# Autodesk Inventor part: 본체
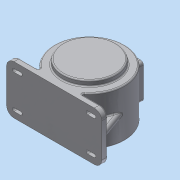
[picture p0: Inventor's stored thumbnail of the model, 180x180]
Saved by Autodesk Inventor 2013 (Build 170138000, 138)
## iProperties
Created: 2415-06
Part Number: 본체
Material: 알루미늄 6061
Document SubType Name: Modeling
Designer: Administrator
Density: 2.71 g/cm^3
Mass: 3262.64 g
Surface Area: 2294.84 cm^2
Volume: 1203.93 cm^3
Author: Administrator
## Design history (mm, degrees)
sketch "스케치1"
  geometry: C1 r 85 at (0, 0); 1 further point
  constraints: 1 centre point, 1 coincident
  dimensions: "d0" = 170 diameter of C1
extrude "돌출1" new body sketch "스케치1" stored distance "d3" = 118; taper "d4" = 0 deg
sketch "스케치2"
  geometry: C1 r 85 at (0, 0) reference; C2 r 65 at (0, 0)
  constraints: 1 centre point, 1 coincident
  dimensions: "d5" = 130 diameter of C2
extrude "돌출2" join sketch "스케치2" distance "d7" = 13; taper "d8" = 0 deg
sketch "스케치3"
  geometry: C1 r 85 at (0, 0) reference; C2 r 65 at (0, 0)
  constraints: 1 centre point, 1 coincident
  dimensions: "d9" = 130 diameter of C2
extrude "돌출3" join sketch "스케치3" distance "d11" = 3; taper "d12" = 0 deg
node "작업 평면1"
sketch "스케치4"
  geometry: L1 (-97, -59)-(97, -59); L2 (115, -41)-(115, 41); L3 (97, 59)-(-97, 59); L4 (-115, 41)-(-115, -41); L5 (-115, -59)-(115, 59); L6 (115, -59)-(-115, 59); A1 r 18 centre (-97, 41) between (-97, 59) and (-115, 41); A2 r 18 centre (-97, -41) between (-115, -41) and (-97, -59); A3 r 18 centre (97, -41) between (97, -59) and (115, -41); A4 r 18 centre (97, 41) between (115, 41) and (97, 59); 3 further points
  constraints: 12 end point, 8 point on circle, 8 point on line, 8 tangent, 4 centre point, 3 equal radius, 3 midpoint, 2 parallel, 1 coincident, 1 horizontal, 1 perpendicular
  dimensions: "d14" = 230 distance of L6.end L5.end; "d15" = 118 distance of L5.end L6.start; "d16" = 18 radius of A1
extrude "돌출4" join sketch "스케치4" distance "d17" = 14; taper "d18" = 0 deg
sketch "스케치5"
  geometry: L1 (0, 41)-(0, -41); L2 (97, 41)-(97, -41); L3 (-97, 41)-(-97, -41); L4 (-97, 50)-(-81, 50); L5 (-97, 32)-(-81, 32); L6 (-81, 45)-(-97, 45); L7 (-97, 37)-(-81, 37); A1 r 9 centre (-97, 41) between (-97, 50) and (-97, 32); A2 r 9 centre (-81, 41) between (-81, 32) and (-81, 50); A3 r 4 centre (-97, 41) between (-97, 45) and (-97, 37); A4 r 4 centre (-81, 41) between (-81, 37) and (-81, 45); 2 further points
  constraints: 14 end point, 8 point on circle, 4 centre point, 4 parallel, 2 coincident, 2 tangent, 1 midpoint, 1 perpendicular, 1 vertical, 3 other
  dimensions: "d19" = 82 distance of L1.start L1.end; "d20" = 97 distance between parallel lines of L3 L1; "d21" = 97 distance between parallel lines of L2 L1 (= d20); "d22" = 18 diameter of A1; "d23" = 16 distance of L4.start L4.end; "d24" = 16 distance of L5.start L5.end; "d25" = 97 distance of L1.start L3.start; "d26" = 81 distance of L1.start A2.centre; "d27" = 8 distance between parallel lines of L6 L7
extrude "돌출5" cut sketch "스케치5" stored distance "d28" = 14; taper "d29" = 0 deg
extrude "돌출6" join sketch "스케치5" distance "d30" = 3; taper "d31" = 0 deg
fillet "모깎기1" dims "d32" = 3
hole "구멍1" diameter "d35" = 95; stored, may be unused: countersink angle "d39" = 90 deg, drill point angle "d41" = 0 deg; dims "d33" = 10, "d34" = 10, "d36" = 6, "d37" = 95, "d38" = 11, "d40" = 11
hole "구멍2" diameter "d44" = 154; stored, may be unused: countersink angle "d48" = 90 deg, drill point angle "d50" = 0 deg; dims "d45" = 6, "d46" = 95, "d47" = 11, "d49" = 98.5, "d120" = 10, "d121" = 10
hole "구멍3" diameter "d53" = 30; stored, may be unused: countersink angle "d57" = 90 deg, drill point angle "d59" = 0 deg; dims "d51" = 10, "d52" = 10, "d54" = 6, "d55" = 47, "d56" = 14, "d58" = 17
node "작업 평면2"
sketch "스케치6"
  geometry: L1 (-35.5, -42.5)-(35.5, -42.5); L2 (42.5, -35.5)-(42.5, 35.5); L3 (35.5, 42.5)-(-35.5, 42.5); L4 (-42.5, 35.5)-(-42.5, -35.5); L5 (-42.5, -42.5)-(42.5, 42.5); L6 (42.5, -42.5)-(-42.5, 42.5); A1 r 7 centre (-35.5, 35.5) between (-35.5, 42.5) and (-42.5, 35.5); A2 r 7 centre (-35.5, -35.5) between (-42.5, -35.5) and (-35.5, -42.5); A3 r 7 centre (35.5, -35.5) between (35.5, -42.5) and (42.5, -35.5); A4 r 7 centre (35.5, 35.5) between (42.5, 35.5) and (35.5, 42.5); 1 further point
  constraints: 12 end point, 8 point on circle, 8 point on line, 8 tangent, 4 centre point, 3 equal radius, 2 midpoint, 2 parallel, 1 horizontal, 1 perpendicular
  dimensions: "d61" = 85 distance of L5.end L6.end; "d63" = 85 distance of L6.start L5.end; "d64" = 7 radius of A1
extrude "돌출7" join sketch "스케치6" stored distance "d65" = 3; taper "d66" = 0 deg
sketch "스케치7"
  geometry: C1 r 35 at (0, 0); 1 further point
  constraints: 1 centre point, 1 coincident
  dimensions: "d67" = 70 diameter of C1
extrude "돌출8" cut sketch "스케치7" stored distance "d69" = 3; taper "d70" = 0 deg
sketch "스케치8"
  geometry: A1 r 55 centre (0, 0) between (0, 55) and (-55, 0); 3 further points
  constraints: 4 point on circle, 2 horizontal alignment, 2 vertical alignment, 1 centre point
  dimensions: "d71" = 110 diameter of A1
hole "구멍4" sketch "스케치8" at (0, 55), (-55, 0), (0, -55), (55, 0) diameter "d73" = 3.242; stored, may be unused: countersink angle "d77" = 90 deg, drill point angle "d79" = 0 deg; dims "d74" = 6, "d75" = 19.05, "d76" = 4.775, "d78" = 17
hole "구멍5" diameter "d82" = 3.242; stored, may be unused: countersink angle "d86" = 90 deg, drill point angle "d88" = 0 deg; dims "d80" = 10, "d81" = 10, "d83" = 10, "d84" = 19.05, "d85" = 4.775, "d87" = 13
hole "구멍6" diameter "d91" = 3.242; stored, may be unused: countersink angle "d95" = 90 deg, drill point angle "d97" = 0 deg; dims "d89" = 10, "d90" = 10, "d92" = 10, "d93" = 19.05, "d94" = 4.775, "d96" = 13
hole "구멍7" diameter "d100" = 3.242; stored, may be unused: countersink angle "d104" = 90 deg, drill point angle "d106" = 0 deg; dims "d98" = 10, "d99" = 10, "d101" = 10, "d102" = 19.05, "d103" = 4.775, "d105" = 13
hole "구멍8" diameter "d109" = 3.242; stored, may be unused: countersink angle "d113" = 90 deg, drill point angle "d115" = 0 deg; dims "d107" = 10, "d108" = 10, "d110" = 10, "d111" = 19.05, "d112" = 4.775, "d114" = 13
fillet "모깎기2" dims "d116" = 0.3
fillet "모깎기4" dims "d118" = 3
fillet "모깎기5" dims "d119" = 3
sketch "스케치9"
  geometry: L1 (-77, 47.5)-(77, 47.5) reference; L2 (0, -67.8)-(0, 70.8) reference; L3 (77, 51)-(77, 47.5); L4 (77, 47.5)-(77, -48) reference; L5 (31, 47.5)-(31, 51); L6 (31, 51)-(29.368, 47.5); L7 (31, 51)-(77, 51); 1 further point
  constraints: 8 end point, 2 parallel, 2 point on line, 1 perpendicular
  dimensions: "d123" = 62 diameter of L5 L2; "d126" = 3.5 distance of L3.start L1.end; "d127" = 115 deg angle of L7 L6
revolve "회전1" sketch "스케치9" stored, may be unused: angle "d128" = 90 deg
sketch "스케치10"
  geometry: 1 further point
fillet "모깎기6" dims "d129" = 3
chamfer "모따기1" distance "d130" = 1; stored, may be unused: second distance "d131" = 2, angle "d132" = 45 deg
chamfer "모따기2" distance "d133" = 1; stored, may be unused: second distance "d134" = 2, angle "d135" = 45 deg
sketch "스케치11"
  geometry: L1 (-115, -85)-(-115, -71) reference; L2 (-97, -71)-(-115, -71) reference; L3 (-97, -71)-(-81, -71) reference; L4 (-115, -85)-(-97, -85) reference; L5 (-109, -71)-(-109, -85); L6 (-69, -71)-(-81, -71) reference; L7 (-46.733, -71)-(-97, -71) reference; L8 (-109, -71)-(-84.87, -4.703); A1 r 85 centre (0, 0) between (46.733, -71) and (-46.733, -71) reference; 1 further point
  constraints: 4 end point, 2 point on line, 1 perpendicular, 1 point on circle
  dimensions: "d141" = 6 distance between parallel lines of L5 L1; "d142" = 110 deg angle of L8 L2
extrude "돌출10" join sketch "스케치11" stored distance "d143" = 15; taper "d144" = 0 deg
fillet "모깎기7" dims "d145" = 3
fillet "모깎기8"
fillet "모깎기9"
fillet "모깎기10" dims "d146" = 3
fillet "모깎기11" dims "d147" = 3
sketch "스케치12"
  geometry: L1 (-161, 0)-(161, 0) reference; L2 (0, 0)-(182.329, 85.021); L3 (56.726, 79.477)-(94.457, -1.436); A1 r 85 centre (0, 0) between (53.953, -65.682) and (-53.953, -65.682) reference
  constraints: 4 end point, 1 perpendicular, 1 tangent
  dimensions: "d148" = 25 deg angle of L2 L1; "d149" = 201.17745 distance of L2.start L2.end; "d150" = 89.27744 distance of L3.start L3.end
node "작업 평면3"
fillet "모깎기12" dims "d154" = 3
sketch "스케치14"
  geometry: L1 (0, 0)-(-115.997, 54.09); L2 (-176.87, 0)-(242.195, 0) reference; L3 (-65.415, 60.843)-(-88.657, 11.002); A1 r 85 centre (0, 0) between (53.953, -65.682) and (-53.953, -65.682) reference; 1 further point
  constraints: 4 end point, 1 midpoint, 1 perpendicular, 1 point on line, 1 tangent
  dimensions: "d155" = 25 deg angle of L1 L2; "d158" = 115.9966 horizontal distance of L1.start L1.end; "d159" = 54.99423 distance of L3.start L3.end
node "작업 평면4"
sketch "스케치15"
  geometry: 2 further points
  constraints: 1 coincident, 1 other
feature "엠보싱2" sketch "스케치15" dims "d160" = 0.5, "d161" = 0
chamfer "모따기3" distance "d162" = 1; stored, may be unused: second distance "d163" = 2, angle "d164" = 45 deg
fillet "모깎기13" dims "d165" = 3
fillet "모깎기14" dims "d166" = 0.3
node "솔리드1"
mirror "대칭1"
mirror "대칭2"
mirror "대칭3"
other parameters: "d13" = -85, "d60" = 88, "d122" = 3.5, "d125" = 115 deg, "d151" = 90 deg
